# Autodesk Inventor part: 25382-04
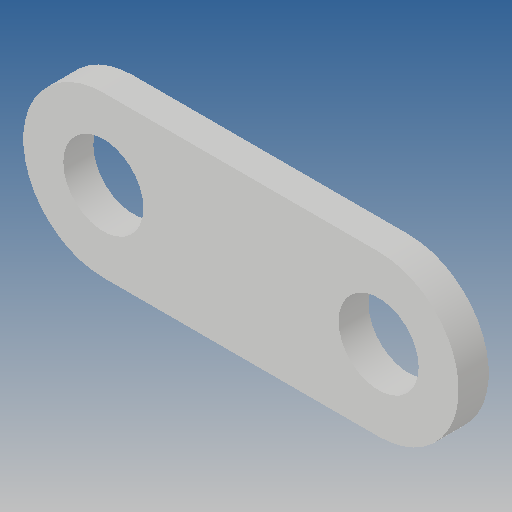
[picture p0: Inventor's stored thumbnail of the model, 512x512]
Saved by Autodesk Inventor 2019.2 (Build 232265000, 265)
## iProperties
Created: 2012-09
Part Number: 25382-04
Material: Ogólny
Document SubType Name: Modeling
Designer: CADENGINEERING4
Density: 1 g/cm^3
Appearance: Domyślna
Author: CADENGINEERING4
Revision Number: ÈÎºÎ
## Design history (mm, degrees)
feature "À­Éì1"
node "Bryła1"
